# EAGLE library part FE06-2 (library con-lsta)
FEMALE HEADER
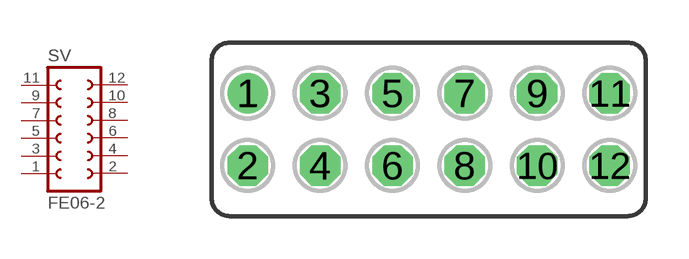
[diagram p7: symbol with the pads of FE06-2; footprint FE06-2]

Designator prefix SV

## FE06-2 (OC_FARNELL: unknown; OC_NEWARK: unknown)  [FE06-2]
1  1  pas
2  2  pas
3  3  pas
4  4  pas
5  5  pas
6  6  pas
7  7  pas
8  8  pas
9  9  pas
10  10  pas
11  11  pas
12  12  pas

## Footprint FE06-2 (pad centres in mm)
FEMALE HEADER
drill 0.914 round: 1 -6.35,1.27
drill 0.914 octagon: 2 -6.35,-1.27; 3 -3.81,1.27; 4 -3.81,-1.27; 5 -1.27,1.27; 6 -1.27,-1.27; 7 1.27,1.27; 8 1.27,-1.27; 9 3.81,1.27; 10 3.81,-1.27; 11 6.35,1.27; 12 6.35,-1.27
